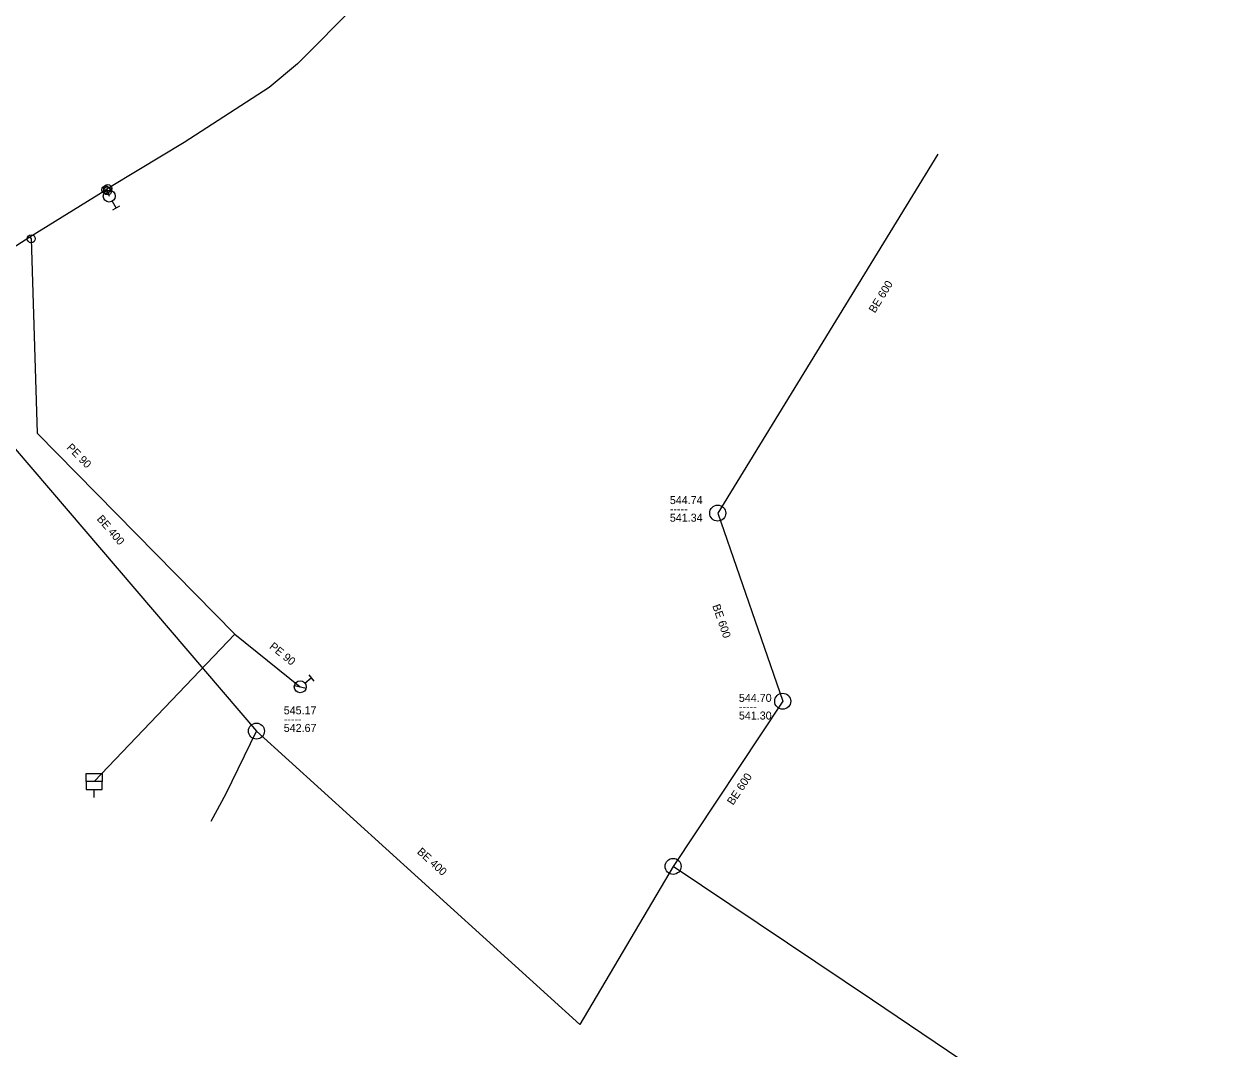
# Model space of a CAD drawing. Extents: x -701133 to -700495, y -1142806 to -1142020.
# Drawn here: x -700700.7 to -700549.5, y -1142526.7 to -1142398.7 of the extents above; entities that cross this region are included whole.
import ezdxf

# ---------------------------------------------------------------- set-up
doc = ezdxf.new("R2010")
doc.units = 0
doc.layers.add('Level 0', color=7, linetype='Continuous')

msp = doc.modelspace()

# ---------------------------------------------------------------- linework, layer by layer
at = {"layer": 'Level 0'}
for p, q in [((-700659.1, -1142396.13), (-700666.57, -1142403.66)), ((-700666.57, -1142403.66), (-700670.13, -1142406.62)), ((-700670.13, -1142406.62), (-700680.76, -1142413.49)), ((-700680.76, -1142413.49), (-700686.4, -1142416.88)), ((-700586.58, -1142414.94), (-700614.07, -1142459.77)), ((-700686.4, -1142416.88), (-700690.29, -1142419.23)), ((-700700.02, -1142425.26), (-700690.55, -1142419.39)), ((-700690.42, -1142419.31), (-700690.55, -1142419.39)), ((-700690.29, -1142419.23), (-700690.42, -1142419.31)), ((-700690.42, -1142419.31), (-700690.32, -1142419.53)), ((-700690.32, -1142419.53), (-700690.11, -1142420.17)), ((-700689.74, -1142420.82), (-700689.26, -1142421.7)), ((-700688.82, -1142421.45), (-700689.69, -1142421.94)), ((-700702.68, -1142426.98), (-700700.02, -1142425.26)), ((-700700.02, -1142425.26), (-700699.86, -1142425.5)), ((-700699.86, -1142425.5), (-700699.1, -1142449.78)), ((-700710.97, -1142441.1), (-700671.71, -1142486.99)), ((-700699.1, -1142449.78), (-700674.43, -1142474.9)), ((-700614.07, -1142459.77), (-700605.95, -1142483.27)), ((-700674.43, -1142474.9), (-700692, -1142493.29)), ((-700674.43, -1142474.9), (-700666.23, -1142481.46)), ((-700665.65, -1142480.99), (-700664.87, -1142480.36)), ((-700665.18, -1142479.97), (-700664.55, -1142480.75)), ((-700666.96, -1142481.29), (-700665.5, -1142481.63)), ((-700605.95, -1142483.27), (-700619.64, -1142503.89)), ((-700675.51, -1142494.79), (-700671.71, -1142486.99)), ((-700671.71, -1142486.99), (-700631.29, -1142523.63)), ((-700692, -1142495.29), (-700692, -1142494.29)), ((-700677.39, -1142498.26), (-700675.51, -1142494.79)), ((-700619.64, -1142503.89), (-700631.29, -1142523.63)), ((-700594.74, -1142520.61), (-700619.64, -1142503.89)), ((-700549.45, -1142551.11), (-700594.74, -1142520.61))]:
    msp.add_line(p, q, dxfattribs=at)
msp.add_lwpolyline([(-700693, -1142493.29), (-700693, -1142492.29), (-700691, -1142492.29), (-700691, -1142493.29)], dxfattribs=at)
msp.add_lwpolyline([(-700693, -1142494.29), (-700691, -1142494.29), (-700691, -1142493.29), (-700693, -1142493.29)], close=True, dxfattribs=at)
for centre, radius in [((-700690.55, -1142419.39), 0.5), ((-700690.11, -1142420.17), 0.75), ((-700690.32, -1142419.53), 0.5), ((-700690.29, -1142419.23), 0.5), ((-700699.86, -1142425.5), 0.5), ((-700614.07, -1142459.77), 1), ((-700666.23, -1142481.46), 0.75), ((-700605.95, -1142483.27), 1), ((-700671.71, -1142486.99), 1), ((-700619.64, -1142503.89), 1)]:
    msp.add_circle(centre, radius, dxfattribs=at)

# ---------------------------------------------------------------- texts
for s, rotation, p in [('BE 600', 58.483, (-700594.42, -1142434.86)), ('PE 90', 314.482, (-700695.51, -1142451.65)), ('BE 400', 310.548, (-700691.72, -1142460.53)), ('BE 600', 289.062, (-700614.76, -1142471.34)), ('PE 90', 321.34, (-700670.18, -1142476.59)), ('BE 600', 56.425, (-700612.15, -1142496.32)), ('BE 400', 317.808, (-700651.72, -1142502.19))]:
    msp.add_text(s, height=1, rotation=rotation, dxfattribs=at).set_placement(p)
for s, p in [('544.74', (-700620.05, -1142458.64)), ('541.34', (-700620.05, -1142460.84)), ('-----', (-700620.05, -1142459.74)), ('544.70', (-700611.42, -1142483.35)), ('545.17', (-700668.3, -1142484.9)), ('541.30', (-700611.42, -1142485.55)), ('-----', (-700611.42, -1142484.45)), ('542.67', (-700668.3, -1142487.1)), ('-----', (-700668.3, -1142486))]:
    msp.add_text(s, height=1, dxfattribs=at).set_placement(p)

doc.saveas('drawing.dxf')
